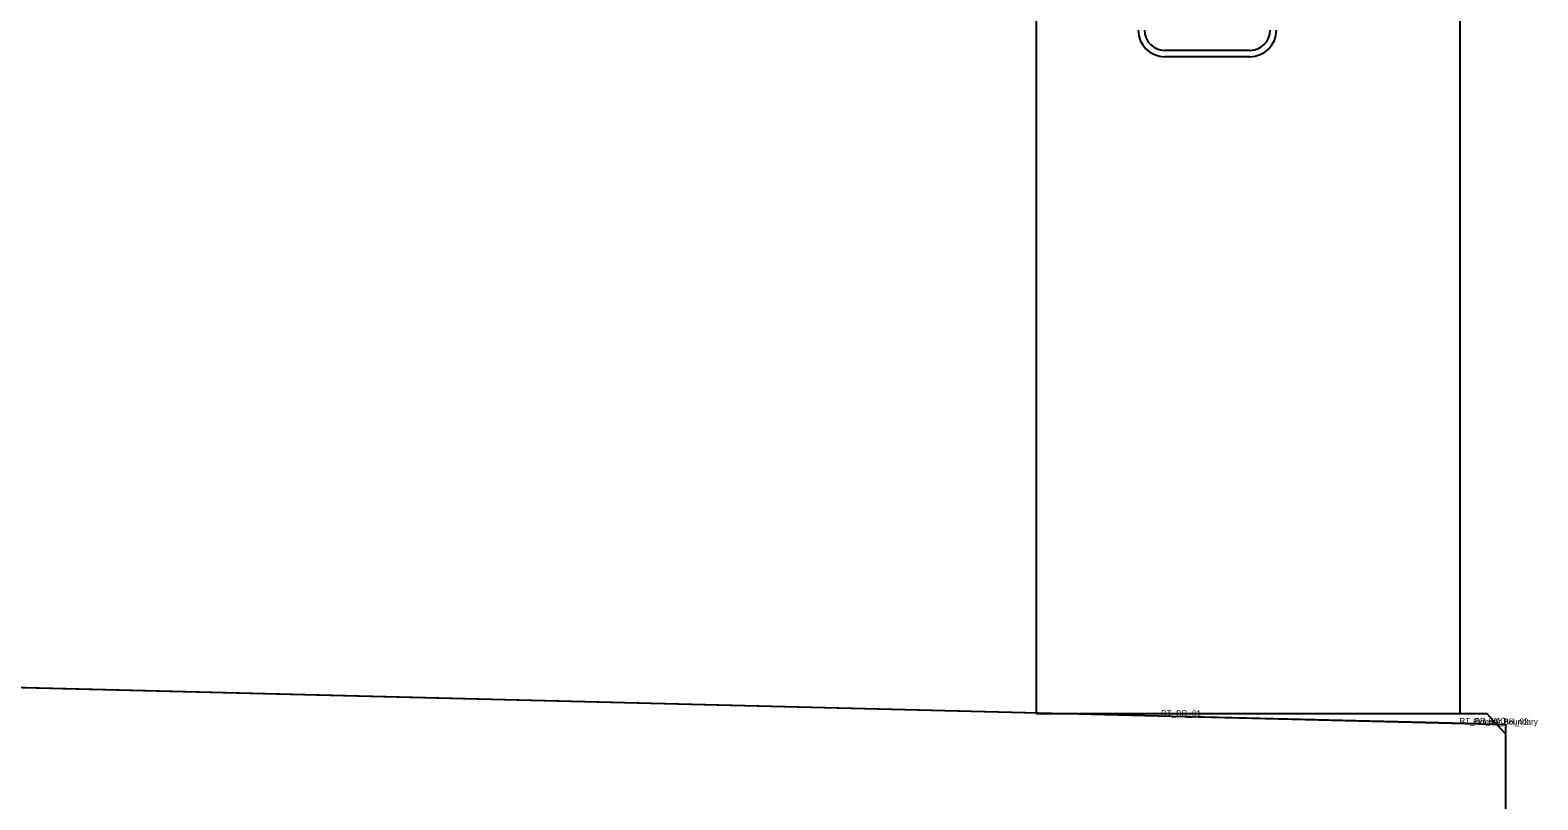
# Model space of a CAD drawing. Extents: x -26 to 4903, y -1010 to 9587.
# Drawn here: x 1170.215 to 1175.191, y 2542.235 to 2544.776 of the extents above; entities that cross this region are included whole.
import ezdxf

# ---------------------------------------------------------------- set-up
doc = ezdxf.new("R2010")
doc.units = 0
for name, color, linetype in [('Default', 7, 'Continuous'), ('Prop CMT Concrete Structures', 7, 'Continuous'), ('Typical Bridge Rail Two Bar CELL', 7, 'Continuous')]:
    doc.layers.add(name, color=color, linetype=linetype)

msp = doc.modelspace()

# ---------------------------------------------------------------- linework, layer by layer
at = {"layer": 'Default'}
for p, q in [((1173.5353, 2545.4512), (1173.5353, 2542.5201)), ((1174.9329, 2545.4512), (1174.9329, 2542.5201)), ((1173.9589, 2544.7095), (1174.2404, 2544.7095)), ((1173.9589, 2544.6886), (1174.2404, 2544.6886)), ((1173.5353, 2542.5201), (1174.9211, 2542.5201)), ((1174.9211, 2542.5201), (1175.0223, 2542.5201)), ((1175.0829, 2542.4536), (1175.0223, 2542.5201))]:
    msp.add_line(p, q, dxfattribs=at)
for points in [[(1149.9999, 2543.1104), (1167.9999, 2542.6604), (1175.0833, 2542.4833)], [(1174.9999, 2542.4854), (1173.9999, 2542.5104)], [(1175.0833, 2542.4833), (1175.0833, 2540.9833)]]:
    msp.add_lwpolyline(points, dxfattribs=at)
for centre, radius, start, end in [((1173.9591, 2544.7759), 0.0876, 180, 270), ((1173.9591, 2544.7759), 0.0667, 180, 270), ((1174.2404, 2544.7759), 0.0667, 270, 0), ((1174.2404, 2544.7759), 0.0876, 270, 0)]:
    msp.add_arc(centre, radius, start, end, dxfattribs=at)
at = {"layer": 'Prop CMT Concrete Structures'}
for p, q in [((1167.9999, 2542.6604), (1175.0833, 2542.4833)), ((1174.9999, 2542.4854), (1173.9999, 2542.5104)), ((1175.0833, 2542.4833), (1175.0833, 2540.9833))]:
    msp.add_line(p, q, dxfattribs=at)
at = {"layer": 'Typical Bridge Rail Two Bar CELL'}
for p, q in [((1173.5353, 2545.4512), (1173.5353, 2542.5201)), ((1174.9329, 2545.4512), (1174.9329, 2542.5201)), ((1173.9589, 2544.7095), (1174.2404, 2544.7095)), ((1173.9589, 2544.6886), (1174.2404, 2544.6886)), ((1173.5353, 2542.5201), (1174.9211, 2542.5201)), ((1174.9211, 2542.5201), (1175.0223, 2542.5201)), ((1175.0829, 2542.4536), (1175.0223, 2542.5201))]:
    msp.add_line(p, q, dxfattribs=at)
for centre, radius, start, end in [((1173.9591, 2544.7759), 0.0876, 180, 270), ((1173.9591, 2544.7759), 0.0667, 180, 270), ((1174.2404, 2544.7759), 0.0667, 270, 0), ((1174.2404, 2544.7759), 0.0876, 270, 0)]:
    msp.add_arc(centre, radius, start, end, dxfattribs=at)

# ---------------------------------------------------------------- texts
at = {"layer": 'Default'}
for s, p in [('RT_BR_01', (1173.9464, 2542.5104)), ('RT_BR_V4O', (1174.9313, 2542.4854)), ('Exterior Boundary', (1174.9765, 2542.4833)), ('RT_BR_02', (1175.0269, 2542.4833))]:
    msp.add_text(s, height=0.02, dxfattribs=at).set_placement(p)

doc.saveas('drawing.dxf')
